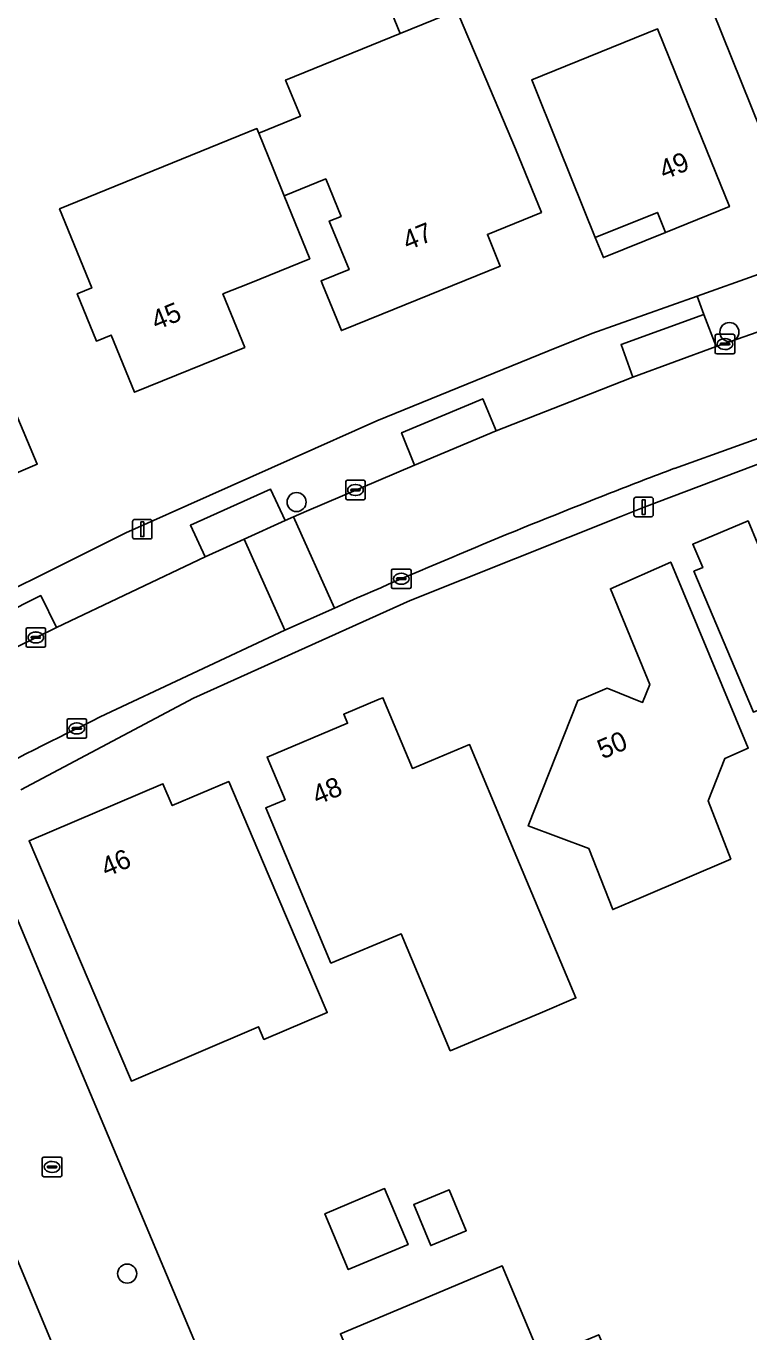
# Model space of a CAD drawing. Extents: x 158472 to 159562, y 388525 to 389606.
# Drawn here: x 158602.1 to 158639.2, y 389117.7 to 389184.7 of the extents above; entities that cross this region are included whole.
import ezdxf

# ---------------------------------------------------------------- set-up
doc = ezdxf.new("R2010")
doc.units = 0
for name, color, linetype in [('IMGEO_Boom', 7, 'Continuous'), ('IMGEO_Erf', 7, 'Continuous'), ('IMGEO_Kolk', 7, 'Continuous'), ('IMGEO_Lichtmast', 7, 'Continuous'), ('IMGEO_Muur', 7, 'Continuous'), ('IMGEO_Pand', 7, 'Continuous'), ('IMGEO_Pand_nummerreeks', 7, 'Continuous'), ('IMGEO_Pand_overbouw', 7, 'Continuous'), ('IMGEO_Parkeervlak_open', 7, 'Continuous'), ('IMGEO_Rijbaan_lokaal_open', 7, 'Continuous'), ('IMGEO_Voetpad_open', 7, 'Continuous')]:
    doc.layers.add(name, color=color, linetype=linetype)

msp = doc.modelspace()

# ---------------------------------------------------------------- linework, layer by layer
at = {"layer": 'IMGEO_Boom'}
for centre in [(158638.224, 389169.023), (158616.005, 389160.3), (158607.307, 389120.711)]:
    msp.add_circle(centre, 0.489, dxfattribs=at)
at = {"layer": 'IMGEO_Erf'}
for points in [[(158661.604, 389189.465), (158664.451, 389182.391), (158661.018, 389181.01), (158657.492, 389179.591), (158654.628, 389186.71), (158648.875, 389184.395), (158643.074, 389182.061), (158645.934, 389174.954), (158642.214, 389173.457), (158640.348, 389178.096), (158631.845, 389199.228)], [(158597.138, 389153.695), (158607.242, 389158.725), (158620.132, 389164.466), (158628.911, 389168.036), (158631.169, 389168.954), (158636.574, 389170.868), (158639.743, 389171.99), (158642.657, 389172.548), (158642.458, 389173.096), (158646.671, 389174.101), (158649.656, 389174.086), (158656.246, 389174.054), (158682.509, 389189.809)], [(158624.237, 389185.527), (158624.753, 389184.309), (158625.296, 389183.025), (158627.244, 389178.42), (158628.578, 389175.163), (158625.8, 389174.032), (158626.459, 389172.411), (158620.373, 389169.935), (158618.306, 389169.094), (158617.358, 389171.425), (158617.267, 389171.647), (158618.697, 389172.228), (158617.686, 389174.713), (158618.288, 389174.957), (158617.506, 389176.88), (158615.37, 389176.011), (158616.681, 389172.787), (158613.57, 389171.522), (158612.227, 389170.976), (158613.343, 389168.232), (158607.687, 389165.932), (158606.493, 389168.868), (158605.733, 389168.559), (158604.747, 389170.984), (158605.487, 389171.286), (158603.837, 389175.343), (158613.967, 389179.462), (158614.063, 389179.226), (158616.198, 389180.094), (158615.442, 389181.955), (158621.318, 389184.341), (158619.362, 389189.159)], [(158641.493, 389162.92), (158633.847, 389160.041), (158632.657, 389159.567), (158621.842, 389155.257), (158610.71, 389150.237), (158601.848, 389145.539)], [(158600.426, 389141.831), (158604.336, 389132.54), (158605.841, 389128.964), (158616.4, 389103.871)], [(158632.28, 389085.631), (158618.202, 389096.374), (158612.964, 389094.303), (158598.129, 389129.848), (158597.07, 389132.386), (158594.354, 389138.893), (158590.94, 389139.667), (158579.773, 389132.914)], [(158618.259, 389117.629), (158622.871, 389119.56), (158626.56, 389121.105), (158628.557, 389116.336)]]:
    msp.add_lwpolyline(points, dxfattribs=at)
for points in [[(158628.074, 389181.962), (158634.54, 389184.575), (158636.351, 389180.093), (158638.224, 389175.457), (158634.945, 389174.133), (158634.528, 389175.165), (158631.341, 389173.877), (158629.468, 389178.513)], [(158590.014, 389169.424), (158593.897, 389171.079), (158594.409, 389172), (158594.254, 389173.112), (158593.723, 389174.358), (158596.948, 389175.733), (158599.537, 389169.66), (158600.734, 389166.852), (158602.695, 389162.252), (158594.55, 389158.78), (158592.589, 389163.38), (158591.392, 389166.189)], [(158636.401, 389156.748), (158636.852, 389156.939), (158636.346, 389158.136), (158639.183, 389159.335), (158639.689, 389158.138), (158641.773, 389159.018), (158642.451, 389157.413), (158645.201, 389158.575), (158647.577, 389152.953), (158640.926, 389150.143), (158639.455, 389149.521)], [(158633.698, 389140.018), (158632.24, 389139.394), (158631.01, 389142.517), (158627.896, 389143.687), (158630.442, 389150.116), (158630.629, 389150.195), (158631.946, 389150.751), (158633.768, 389150.023), (158634.132, 389150.934), (158632.117, 389155.854), (158635.216, 389157.224), (158639.196, 389147.677), (158637.985, 389147.141), (158637.128, 389144.977), (158638.295, 389141.983)], [(158630.345, 389134.856), (158628.502, 389134.083), (158623.891, 389132.147), (158621.37, 389138.152), (158617.769, 389136.641), (158614.423, 389144.613), (158615.413, 389145.028), (158614.494, 389147.219), (158618.622, 389148.952), (158618.428, 389149.414), (158620.249, 389150.179), (158620.433, 389150.256), (158621.955, 389146.63), (158624.887, 389147.86), (158626.822, 389143.25)], [(158617.576, 389134.109), (158614.33, 389132.725), (158614.054, 389133.375), (158607.526, 389130.591), (158606.331, 389133.394), (158602.27, 389142.917), (158609.144, 389145.847), (158609.623, 389144.725), (158612.522, 389145.962), (158614.548, 389141.211)], [(158621.725, 389122.204), (158618.659, 389120.92), (158617.459, 389123.787), (158620.524, 389125.071)], [(158624.713, 389122.914), (158622.896, 389122.153), (158622.016, 389124.253), (158623.833, 389125.014)]]:
    msp.add_lwpolyline(points, close=True, dxfattribs=at)
at = {"layer": 'IMGEO_Kolk'}
for p, q in [((158637.496, 389167.98), (158637.496, 389168.832)), ((158637.571, 389168.906), (158638.423, 389168.906)), ((158637.984, 389168.686), (158638.009, 389168.686)), ((158638.497, 389168.832), (158638.497, 389167.98)), ((158638.423, 389167.906), (158637.571, 389167.906)), ((158637.755, 389168.4), (158637.755, 389168.412)), ((158638.193, 389168.363), (158637.795, 389168.363)), ((158637.798, 389168.449), (158638.196, 389168.449)), ((158638.007, 389168.126), (158637.982, 389168.126)), ((158638.239, 389168.412), (158638.239, 389168.4)), ((158618.529, 389160.493), (158618.529, 389161.345)), ((158618.604, 389161.419), (158619.456, 389161.419)), ((158619.017, 389161.199), (158619.042, 389161.199)), ((158619.53, 389161.345), (158619.53, 389160.493)), ((158618.788, 389160.913), (158618.788, 389160.925)), ((158619.226, 389160.876), (158618.828, 389160.876)), ((158618.831, 389160.962), (158619.229, 389160.962)), ((158619.04, 389160.639), (158619.015, 389160.639)), ((158619.272, 389160.925), (158619.272, 389160.913)), ((158619.456, 389160.419), (158618.604, 389160.419)), ((158620.879, 389155.938), (158620.879, 389156.79)), ((158620.954, 389156.864), (158621.806, 389156.864)), ((158621.367, 389156.644), (158621.392, 389156.644)), ((158621.88, 389156.79), (158621.88, 389155.938)), ((158621.806, 389155.864), (158620.954, 389155.864)), ((158621.138, 389156.358), (158621.138, 389156.37)), ((158621.576, 389156.321), (158621.178, 389156.321)), ((158621.181, 389156.407), (158621.579, 389156.407)), ((158621.39, 389156.084), (158621.365, 389156.084)), ((158621.622, 389156.37), (158621.622, 389156.358)), ((158602.119, 389152.927), (158602.119, 389153.779)), ((158602.194, 389153.853), (158603.046, 389153.853)), ((158603.12, 389153.779), (158603.12, 389152.927)), ((158602.378, 389153.347), (158602.378, 389153.359)), ((158602.816, 389153.31), (158602.418, 389153.31)), ((158602.421, 389153.396), (158602.819, 389153.396)), ((158602.63, 389153.073), (158602.605, 389153.073)), ((158602.607, 389153.633), (158602.632, 389153.633)), ((158602.862, 389153.359), (158602.862, 389153.347)), ((158603.046, 389152.853), (158602.194, 389152.853)), ((158604.221, 389148.259), (158604.221, 389149.111)), ((158604.296, 389149.185), (158605.148, 389149.185)), ((158605.222, 389149.111), (158605.222, 389148.259)), ((158604.48, 389148.679), (158604.48, 389148.691)), ((158604.918, 389148.642), (158604.52, 389148.642)), ((158604.523, 389148.728), (158604.921, 389148.728)), ((158604.732, 389148.405), (158604.707, 389148.405)), ((158604.709, 389148.965), (158604.734, 389148.965)), ((158604.964, 389148.691), (158604.964, 389148.679)), ((158605.148, 389148.185), (158604.296, 389148.185)), ((158602.951, 389125.76), (158602.951, 389126.612)), ((158603.026, 389126.686), (158603.878, 389126.686)), ((158603.439, 389126.466), (158603.464, 389126.466)), ((158603.952, 389126.612), (158603.952, 389125.76)), ((158603.878, 389125.686), (158603.026, 389125.686)), ((158603.21, 389126.18), (158603.21, 389126.192)), ((158603.648, 389126.143), (158603.25, 389126.143)), ((158603.253, 389126.229), (158603.651, 389126.229)), ((158603.462, 389125.906), (158603.437, 389125.906)), ((158603.694, 389126.192), (158603.694, 389126.18))]:
    msp.add_line(p, q, dxfattribs=at)
for points in [[(158637.496, 389167.98), (158637.496, 389168.832)], [(158637.571, 389168.906), (158638.423, 389168.906)], [(158638.497, 389168.832), (158638.497, 389167.98)], [(158638.423, 389167.906), (158637.571, 389167.906)], [(158618.529, 389160.493), (158618.529, 389161.345)], [(158618.604, 389161.419), (158619.456, 389161.419)], [(158619.53, 389161.345), (158619.53, 389160.493)], [(158619.456, 389160.419), (158618.604, 389160.419)], [(158620.879, 389155.938), (158620.879, 389156.79)], [(158620.954, 389156.864), (158621.806, 389156.864)], [(158621.88, 389156.79), (158621.88, 389155.938)], [(158621.806, 389155.864), (158620.954, 389155.864)], [(158602.119, 389152.927), (158602.119, 389153.779)], [(158602.194, 389153.853), (158603.046, 389153.853)], [(158603.12, 389153.779), (158603.12, 389152.927)], [(158603.046, 389152.853), (158602.194, 389152.853)], [(158604.221, 389148.259), (158604.221, 389149.111)], [(158604.296, 389149.185), (158605.148, 389149.185)], [(158605.222, 389149.111), (158605.222, 389148.259)], [(158605.148, 389148.185), (158604.296, 389148.185)], [(158602.951, 389125.76), (158602.951, 389126.612)], [(158603.026, 389126.686), (158603.878, 389126.686)], [(158603.952, 389126.612), (158603.952, 389125.76)], [(158603.878, 389125.686), (158603.026, 389125.686)]]:
    msp.add_lwpolyline(points, dxfattribs=at)
for centre, radius, start, end in [((158637.573, 389168.83), 0.0765, 91.55205, 178.44795), ((158637.573, 389168.83), 0.0765, 91.55205, 178.44795), ((158638.421, 389168.83), 0.0765, 1.55205, 88.44795), ((158638.421, 389168.83), 0.0765, 1.55205, 88.44795), ((158637.573, 389167.982), 0.0765, 181.55205, 268.44795), ((158637.573, 389167.982), 0.0765, 181.55205, 268.44795), ((158637.795, 389168.409), 0.0403, 85.87752, 175.75265), ((158637.792, 389168.399), 0.0366, 178.93798, 274.71019), ((158638.196, 389168.406), 0.043, 264.86636, 352.45326), ((158638.2, 389168.411), 0.0386, 1.73085, 96.63898), ((158638.421, 389167.982), 0.0765, 271.55205, 358.44795), ((158638.421, 389167.982), 0.0765, 271.55205, 358.44795), ((158618.606, 389161.343), 0.0765, 91.55205, 178.44795), ((158618.606, 389161.343), 0.0765, 91.55205, 178.44795), ((158619.454, 389161.343), 0.0765, 1.55205, 88.44795), ((158619.454, 389161.343), 0.0765, 1.55205, 88.44795), ((158618.606, 389160.495), 0.0765, 181.55205, 268.44795), ((158618.606, 389160.495), 0.0765, 181.55205, 268.44795), ((158618.828, 389160.922), 0.0403, 85.87752, 175.75265), ((158618.825, 389160.912), 0.0366, 178.93798, 274.71019), ((158619.229, 389160.919), 0.043, 264.86636, 352.45326), ((158619.233, 389160.924), 0.0386, 1.73085, 96.63898), ((158619.454, 389160.495), 0.0765, 271.55205, 358.44795), ((158619.454, 389160.495), 0.0765, 271.55205, 358.44795), ((158620.956, 389156.788), 0.0765, 91.55205, 178.44795), ((158620.956, 389156.788), 0.0765, 91.55205, 178.44795), ((158621.804, 389156.788), 0.0765, 1.55205, 88.44795), ((158621.804, 389156.788), 0.0765, 1.55205, 88.44795), ((158620.956, 389155.94), 0.0765, 181.55205, 268.44795), ((158620.956, 389155.94), 0.0765, 181.55205, 268.44795), ((158621.178, 389156.367), 0.0403, 85.87752, 175.75265), ((158621.175, 389156.357), 0.0366, 178.93798, 274.71019), ((158621.579, 389156.364), 0.043, 264.86636, 352.45326), ((158621.583, 389156.369), 0.0386, 1.73085, 96.63898), ((158621.804, 389155.94), 0.0765, 271.55205, 358.44795), ((158621.804, 389155.94), 0.0765, 271.55205, 358.44795), ((158602.196, 389153.777), 0.0765, 91.55205, 178.44795), ((158602.196, 389153.777), 0.0765, 91.55205, 178.44795), ((158603.044, 389153.777), 0.0765, 1.55205, 88.44795), ((158603.044, 389153.777), 0.0765, 1.55205, 88.44795), ((158602.418, 389153.356), 0.0403, 85.87752, 175.75265), ((158602.415, 389153.346), 0.0366, 178.93798, 274.71019), ((158602.819, 389153.353), 0.043, 264.86636, 352.45326), ((158602.823, 389153.358), 0.0386, 1.73085, 96.63898), ((158602.196, 389152.929), 0.0765, 181.55205, 268.44795), ((158602.196, 389152.929), 0.0765, 181.55205, 268.44795), ((158603.044, 389152.929), 0.0765, 271.55205, 358.44795), ((158603.044, 389152.929), 0.0765, 271.55205, 358.44795), ((158604.298, 389149.109), 0.0765, 91.55205, 178.44795), ((158604.298, 389149.109), 0.0765, 91.55205, 178.44795), ((158605.146, 389149.109), 0.0765, 1.55205, 88.44795), ((158605.146, 389149.109), 0.0765, 1.55205, 88.44795), ((158604.52, 389148.688), 0.0403, 85.87752, 175.75265), ((158604.517, 389148.678), 0.0366, 178.93798, 274.71019), ((158604.921, 389148.685), 0.043, 264.86636, 352.45326), ((158604.925, 389148.69), 0.0386, 1.73085, 96.63898), ((158604.298, 389148.261), 0.0765, 181.55205, 268.44795), ((158604.298, 389148.261), 0.0765, 181.55205, 268.44795), ((158605.146, 389148.261), 0.0765, 271.55205, 358.44795), ((158605.146, 389148.261), 0.0765, 271.55205, 358.44795), ((158603.028, 389126.61), 0.0765, 91.55205, 178.44795), ((158603.028, 389126.61), 0.0765, 91.55205, 178.44795), ((158603.876, 389126.61), 0.0765, 1.55205, 88.44795), ((158603.876, 389126.61), 0.0765, 1.55205, 88.44795), ((158603.028, 389125.762), 0.0765, 181.55205, 268.44795), ((158603.028, 389125.762), 0.0765, 181.55205, 268.44795), ((158603.25, 389126.189), 0.0403, 85.87752, 175.75265), ((158603.247, 389126.179), 0.0366, 178.93798, 274.71019), ((158603.651, 389126.186), 0.043, 264.86636, 352.45326), ((158603.655, 389126.191), 0.0386, 1.73085, 96.63898), ((158603.876, 389125.762), 0.0765, 271.55205, 358.44795), ((158603.876, 389125.762), 0.0765, 271.55205, 358.44795)]:
    msp.add_arc(centre, radius, start, end, dxfattribs=at)
for centre, major_axis, ratio, start_param, end_param in [((158637.983, 389168.406), (-0.387, 0.002), 0.722429, 4.712389, 7.853982), ((158638.008, 389168.406), (-0.39, 0.002), 0.717154, 1.570796, 4.712389), ((158619.016, 389160.919), (-0.387, 0.002), 0.722429, 4.712389, 7.853982), ((158619.041, 389160.919), (-0.39, 0.002), 0.717154, 1.570796, 4.712389), ((158621.366, 389156.364), (-0.387, 0.002), 0.722429, 4.712389, 7.853982), ((158621.391, 389156.364), (-0.39, 0.002), 0.717154, 1.570796, 4.712389), ((158602.606, 389153.353), (-0.387, 0.002), 0.722429, 4.712389, 7.853982), ((158602.631, 389153.353), (-0.39, 0.002), 0.717154, 1.570796, 4.712389), ((158604.708, 389148.685), (-0.387, 0.002), 0.722429, 4.712389, 7.853982), ((158604.733, 389148.685), (-0.39, 0.002), 0.717154, 1.570796, 4.712389), ((158603.438, 389126.186), (-0.387, 0.002), 0.722429, 4.712389, 7.853982), ((158603.463, 389126.186), (-0.39, 0.002), 0.717154, 1.570796, 4.712389)]:
    msp.add_ellipse(centre, major_axis=major_axis, ratio=ratio, start_param=start_param, end_param=end_param, dxfattribs=at)
at = {"layer": 'IMGEO_Lichtmast'}
for p, q in [((158633.323, 389159.645), (158633.323, 389160.445)), ((158633.323, 389160.445), (158633.323, 389159.645)), ((158633.423, 389160.545), (158634.213, 389160.545)), ((158634.213, 389160.545), (158633.423, 389160.545)), ((158634.313, 389160.445), (158634.313, 389159.645)), ((158634.313, 389159.645), (158634.313, 389160.445)), ((158607.589, 389158.505), (158607.589, 389159.305)), ((158607.589, 389159.305), (158607.589, 389158.505)), ((158607.689, 389159.405), (158608.479, 389159.405)), ((158608.479, 389159.405), (158607.689, 389159.405)), ((158608.579, 389159.305), (158608.579, 389158.505)), ((158608.579, 389158.505), (158608.579, 389159.305)), ((158634.213, 389159.545), (158633.423, 389159.545)), ((158633.423, 389159.545), (158634.213, 389159.545)), ((158608.479, 389158.405), (158607.689, 389158.405)), ((158607.689, 389158.405), (158608.479, 389158.405))]:
    msp.add_line(p, q, dxfattribs=at)
for points in [[(158633.743, 389160.42), (158633.893, 389160.42), (158633.893, 389159.67), (158633.743, 389159.67), (158633.743, 389160.42)], [(158608.009, 389159.28), (158608.159, 389159.28), (158608.159, 389158.53), (158608.009, 389158.53), (158608.009, 389159.28)]]:
    msp.add_lwpolyline(points, dxfattribs=at)
for centre, start, end in [((158633.423, 389160.445), 90, 180), ((158633.423, 389160.445), 90, 180), ((158634.213, 389160.445), 0, 90), ((158634.213, 389160.445), 360, 90), ((158607.689, 389159.305), 90, 180), ((158607.689, 389159.305), 90, 180), ((158608.479, 389159.305), 0, 90), ((158608.479, 389159.305), 360, 90), ((158633.423, 389159.645), 180, 270), ((158633.423, 389159.645), 180, 270), ((158634.213, 389159.645), 270, 0), ((158634.213, 389159.645), 270, 0), ((158607.689, 389158.505), 180, 270), ((158607.689, 389158.505), 180, 270), ((158608.479, 389158.505), 270, 0), ((158608.479, 389158.505), 270, 0)]:
    msp.add_arc(centre, 0.1, start, end, dxfattribs=at)
at = {"layer": 'IMGEO_Muur'}
msp.add_lwpolyline([(158604.336, 389132.54), (158605.841, 389128.964)], dxfattribs=at)
at = {"layer": 'IMGEO_Pand'}
for points in [[(158645.427, 389192.787), (158640.548, 389190.824), (158636.425, 389201.071), (158631.845, 389199.228), (158640.348, 389178.096), (158642.214, 389173.457), (158645.934, 389174.954), (158643.074, 389182.061), (158648.875, 389184.395), (158645.47, 389192.68)], [(158621.318, 389184.341), (158624.237, 389185.527), (158622.21, 389190.315), (158619.362, 389189.159)], [(158621.318, 389184.341), (158615.442, 389181.955), (158616.198, 389180.094), (158614.063, 389179.226), (158614.798, 389177.419), (158615.37, 389176.011), (158617.506, 389176.88), (158618.288, 389174.957), (158617.686, 389174.713), (158618.697, 389172.228), (158617.267, 389171.647), (158617.358, 389171.425), (158618.306, 389169.094), (158620.373, 389169.935), (158626.459, 389172.411), (158625.8, 389174.032), (158628.578, 389175.163), (158627.244, 389178.42), (158625.296, 389183.025), (158624.753, 389184.309), (158624.237, 389185.527)], [(158636.351, 389180.093), (158634.54, 389184.575), (158628.074, 389181.962), (158629.468, 389178.513), (158631.341, 389173.877), (158634.528, 389175.165), (158634.945, 389174.133), (158638.224, 389175.457)], [(158616.681, 389172.787), (158615.37, 389176.011), (158614.798, 389177.419), (158614.063, 389179.226), (158613.967, 389179.462), (158603.837, 389175.343), (158605.487, 389171.286), (158604.747, 389170.984), (158605.733, 389168.559), (158606.493, 389168.868), (158607.687, 389165.932), (158613.343, 389168.232), (158612.227, 389170.976), (158613.57, 389171.522)], [(158600.734, 389166.852), (158599.537, 389169.66), (158596.948, 389175.733), (158593.723, 389174.358), (158594.254, 389173.112), (158594.409, 389172), (158593.897, 389171.079), (158590.014, 389169.424), (158591.392, 389166.189), (158592.589, 389163.38), (158594.55, 389158.78), (158602.695, 389162.252)], [(158640.926, 389150.143), (158647.577, 389152.953), (158645.201, 389158.575), (158642.451, 389157.413), (158641.773, 389159.018), (158639.689, 389158.138), (158639.183, 389159.335), (158636.346, 389158.136), (158636.852, 389156.939), (158636.401, 389156.748), (158639.455, 389149.521)], [(158627.896, 389143.687), (158631.01, 389142.517), (158632.24, 389139.394), (158633.698, 389140.018), (158638.295, 389141.983), (158637.128, 389144.977), (158637.985, 389147.141), (158639.196, 389147.677), (158635.216, 389157.224), (158632.117, 389155.854), (158634.132, 389150.934), (158633.768, 389150.023), (158631.946, 389150.751), (158630.629, 389150.195), (158630.442, 389150.116)], [(158628.502, 389134.083), (158630.345, 389134.856), (158626.822, 389143.25), (158624.887, 389147.86), (158621.955, 389146.63), (158620.433, 389150.256), (158620.249, 389150.179), (158618.428, 389149.414), (158618.622, 389148.952), (158614.494, 389147.219), (158615.413, 389145.028), (158614.423, 389144.613), (158617.769, 389136.641), (158621.37, 389138.152), (158623.891, 389132.147)], [(158614.548, 389141.211), (158612.522, 389145.962), (158609.623, 389144.725), (158609.144, 389145.847), (158602.27, 389142.917), (158606.331, 389133.394), (158607.526, 389130.591), (158614.054, 389133.375), (158614.33, 389132.725), (158617.576, 389134.109)], [(158617.459, 389123.787), (158618.659, 389120.92), (158621.725, 389122.204), (158620.524, 389125.071)], [(158622.016, 389124.253), (158622.896, 389122.153), (158624.713, 389122.914), (158623.833, 389125.014)], [(158627.265, 389110.433), (158632.753, 389114.612), (158631.513, 389117.574), (158628.557, 389116.336), (158626.56, 389121.105), (158622.871, 389119.56), (158618.259, 389117.629), (158620.62, 389111.989), (158625.72, 389114.124)]]:
    msp.add_lwpolyline(points, close=True, dxfattribs=at)
at = {"layer": 'IMGEO_Pand_overbouw'}
msp.add_lwpolyline([(158634.945, 389174.133), (158634.528, 389175.165), (158631.341, 389173.877), (158631.758, 389172.846)], close=True, dxfattribs=at)
at = {"layer": 'IMGEO_Parkeervlak_open'}
for points in [[(158637.553, 389168.276), (158636.916, 389169.918), (158632.664, 389168.385), (158633.271, 389166.705)], [(158626.256, 389163.948), (158625.565, 389165.6), (158621.395, 389163.854), (158622.064, 389162.197)], [(158615.423, 389159.358), (158614.665, 389160.968), (158610.557, 389159.108), (158611.31, 389157.497), (158613.307, 389158.401)], [(158603.678, 389153.872), (158602.868, 389155.501), (158598.828, 389153.465), (158599.62, 389151.872)]]:
    msp.add_lwpolyline(points, close=True, dxfattribs=at)
at = {"layer": 'IMGEO_Rijbaan_lokaal_open'}
for points in [[(158640.38, 389169.266), (158637.553, 389168.276), (158633.271, 389166.705), (158630.058, 389165.442), (158626.256, 389163.948), (158622.064, 389162.197), (158616.512, 389159.83), (158615.843, 389159.54), (158617.944, 389154.862), (158619.114, 389155.378)], [(158635.412, 389162.03), (158641.867, 389164.341)], [(158641.867, 389164.341), (158635.412, 389162.03)], [(158601.848, 389145.539), (158610.71, 389150.237), (158621.842, 389155.257), (158632.657, 389159.567), (158633.847, 389160.041), (158641.493, 389162.92)], [(158605.926, 389149.273), (158615.407, 389153.725), (158613.307, 389158.401), (158611.31, 389157.497), (158603.678, 389153.872), (158599.62, 389151.872)], [(158619.114, 389155.378), (158617.944, 389154.862), (158615.407, 389153.725), (158605.926, 389149.273)], [(158697.03, 389045.201), (158668.409, 389067.056), (158666.009, 389068.886), (158618.796, 389104.84), (158616.4, 389103.871), (158605.841, 389128.964), (158604.336, 389132.54), (158600.426, 389141.831)], [(158598.129, 389129.848), (158612.964, 389094.303), (158618.202, 389096.374), (158632.28, 389085.631), (158640.886, 389079.099), (158643.071, 389077.441), (158651.434, 389071.094), (158652.585, 389070.22), (158655.228, 389073.702), (158657.155, 389072.238), (158654.513, 389068.757), (158654.128, 389060.291), (158653.115, 389059.863), (158654.819, 389055.829), (158652.258, 389054.748), (158650.554, 389058.782), (158646.219, 389056.952), (158643.914, 389055.983), (158639.056, 389053.929), (158594.001, 389034.936)]]:
    msp.add_lwpolyline(points, dxfattribs=at)
msp.add_lwpolyline([(158615.407, 389153.725), (158617.944, 389154.862), (158615.843, 389159.54), (158615.423, 389159.358), (158613.307, 389158.401)], close=True, dxfattribs=at)
for centre, radius, start, end in [((158740.469, 388883.487), 297.697, 110.6648, 111.34246), ((158740.469, 388883.487), 297.697, 110.6648, 111.34246), ((158752.706, 388851.297), 332.132, 111.28767, 113.71734), ((158752.706, 388851.297), 332.132, 111.28767, 113.71734), ((158739.429, 388875.529), 304.563, 115.99818, 118.84758), ((158739.429, 388875.529), 304.563, 115.99818, 118.84758)]:
    msp.add_arc(centre, radius, start, end, dxfattribs=at)
at = {"layer": 'IMGEO_Voetpad_open'}
for points in [[(158649.656, 389174.086), (158646.671, 389174.101), (158642.458, 389173.096), (158642.657, 389172.548), (158639.743, 389171.99), (158636.574, 389170.868), (158636.916, 389169.918), (158637.553, 389168.276), (158640.38, 389169.266)], [(158599.62, 389151.872), (158598.828, 389153.465), (158602.868, 389155.501), (158603.678, 389153.872), (158611.31, 389157.497), (158610.557, 389159.108), (158614.665, 389160.968), (158615.423, 389159.358), (158615.843, 389159.54), (158616.512, 389159.83), (158622.064, 389162.197), (158621.395, 389163.854), (158625.565, 389165.6), (158626.256, 389163.948), (158630.058, 389165.442), (158633.271, 389166.705), (158632.664, 389168.385), (158636.916, 389169.918), (158636.574, 389170.868), (158631.169, 389168.954), (158628.911, 389168.036), (158620.132, 389164.466), (158607.242, 389158.725), (158597.138, 389153.695)]]:
    msp.add_lwpolyline(points, dxfattribs=at)

# ---------------------------------------------------------------- texts
at = {"layer": 'IMGEO_Pand_nummerreeks'}
for s, rotation, p in [('49', 21.98795, (158634.875, 389176.822)), ('47', 22.13909, (158621.702, 389173.196)), ('45', 22.12763, (158608.8, 389169.105)), ('50', 22.88983, (158631.712, 389147.092)), ('48', 22.77344, (158617.069, 389144.743)), ('46', 23.08583, (158606.233, 389141.041))]:
    msp.add_text(s, height=1, rotation=rotation, dxfattribs=at).set_placement(p)

doc.saveas('drawing.dxf')
